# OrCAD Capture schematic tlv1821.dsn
size A
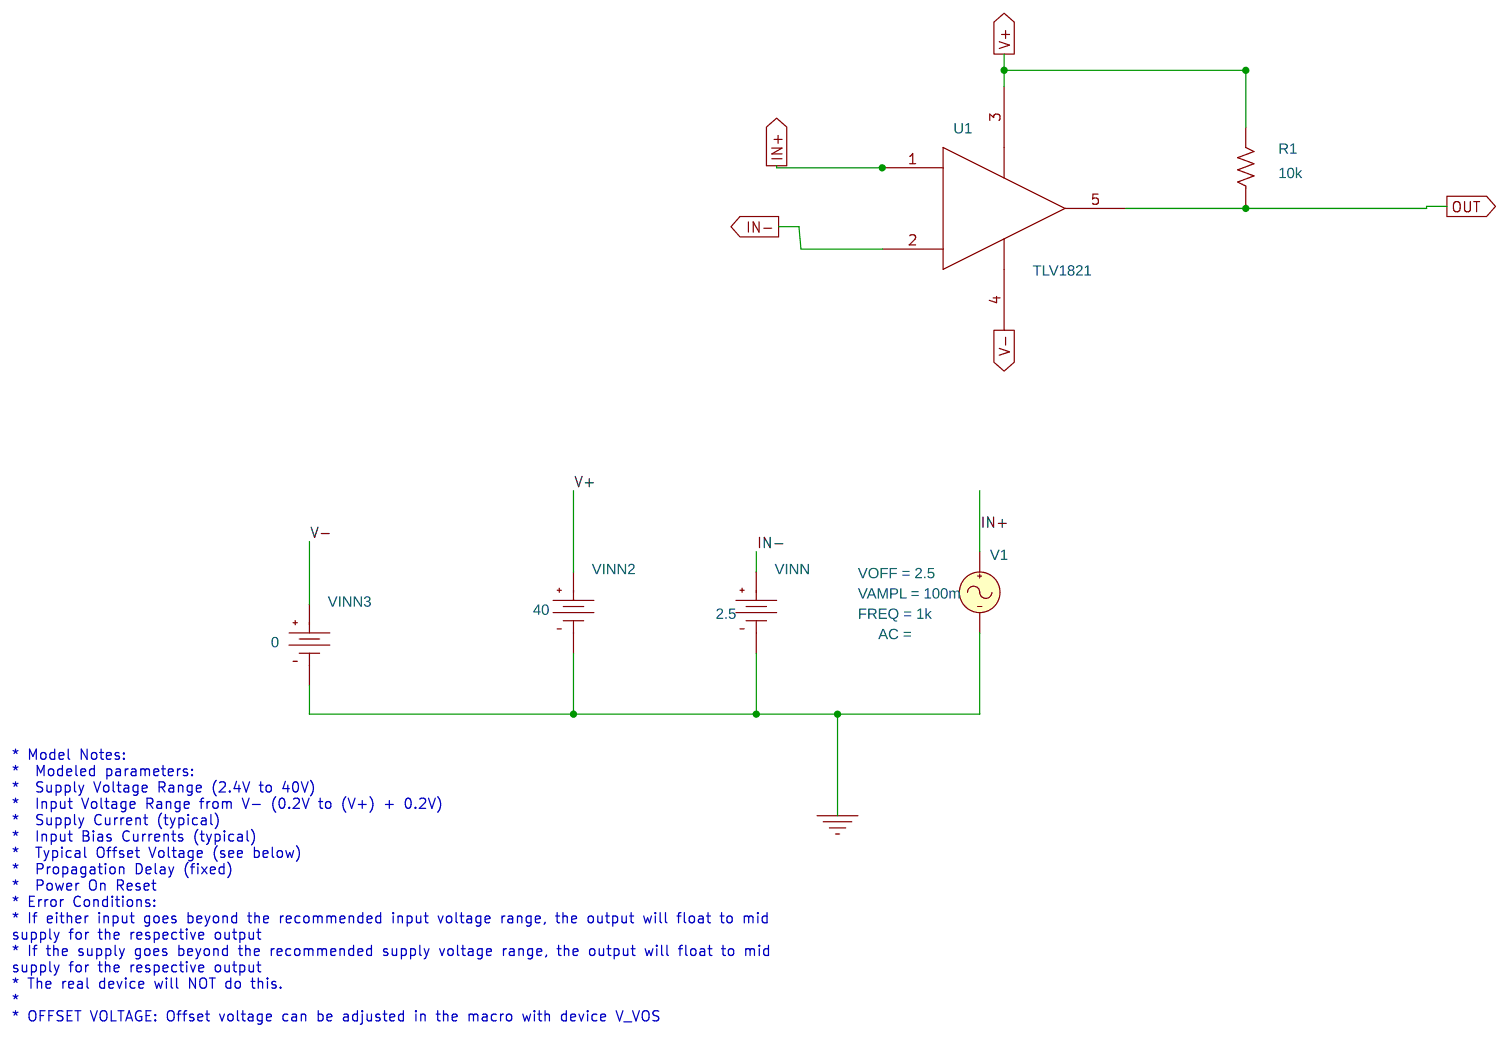
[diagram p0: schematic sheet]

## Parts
R1  10k  [AXRC05]
U1  TLV1821
V1  VSIN
VINN  VDC
VINN2  VDC
VINN3  VDC

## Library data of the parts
R1 = R
U1 = TLV1821
V1 = VSIN: FREQ: 1k; VAMPL: 100m; VOFF: 2.5
VINN = VDC: DC: 2.5
VINN2 = VDC: DC: 40
VINN3 = VDC: DC: 0

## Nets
0: V1.2(-) VINN.1(-) VINN2.1(-) VINN3.1(-)
IN+: U1.1(IN+) V1.1(+)
IN-: U1.2(IN-) VINN.0(+)
OUT: R1.1 U1.5(OUT)
V+: R1.2 U1.3(V+) VINN2.0(+)
V-: U1.4(V-) VINN3.0(+)

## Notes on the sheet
- * Model Notes:
  *  Modeled parameters:
  *  Supply Voltage Range (2.4V to 40V)
  *  Input Voltage Range from V- (0.2V to (V+) + 0.2V)
  *  Supply Current (typical)
  *  Input Bias Currents (typical)
  *  Typical Offset Voltage (see below)
  *  Propagation Delay (fixed)
  *  Power On Reset
  * Error Conditions:
  * If either input goes beyond the recommended input voltage range, the output will float to mid
  supply for the respective output
  * If the supply goes beyond the recommended supply voltage range, the output will float to mid
  supply for the respective output
  * The real device will NOT do this.
  *
  * OFFSET VOLTAGE: Offset voltage can be adjusted in the macro with device V_VOS
